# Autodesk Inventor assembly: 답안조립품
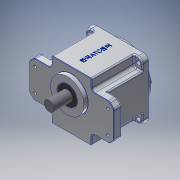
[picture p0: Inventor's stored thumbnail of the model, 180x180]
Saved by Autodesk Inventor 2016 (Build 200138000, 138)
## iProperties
Created: 2017-01
Part Number: 답안조립품
Material: 일반
Document SubType Name: Assembly
Designer: Owner
Author: Owner
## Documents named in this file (10)
- C:\Users\Owner\Desktop\470111V1001\답안조립품.iam
- C:\Users\Owner\Desktop\470111V1001\본체.ipt
- C:\Users\Owner\Desktop\470111V1001\메인축.ipt
- C:\Users\Owner\Desktop\470111V1001\베어링 608.ipt
- C:\Users\Owner\Desktop\470111V1001\베어링 6003.ipt
- C:\Users\Owner\Desktop\470111V1001\볼트 M4 x 10.ipt
- C:\Users\Owner\Desktop\470111V1001\서브축.ipt
- C:\Users\Owner\Desktop\470111V1001\오일실 8 22 7.ipt
- C:\Users\Owner\Desktop\470111V1001\오일실 17 32 8.ipt
- C:\Users\Owner\Desktop\470111V1001\커버.ipt
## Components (2 placed, 1 different names)
1. ISO 4762 M4 x 10:1
2. ISO 4762 M4 x 10:2
